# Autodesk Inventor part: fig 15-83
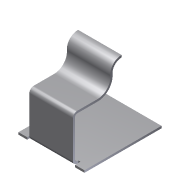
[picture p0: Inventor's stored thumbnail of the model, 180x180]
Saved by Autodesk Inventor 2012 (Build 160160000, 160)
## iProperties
Shininess: 77.0
Angle Display Precision: 2
Document Length Units: 11269
Document Angle Units: 11279
Document Time Units: 11290
Document Mass Units: 11283
Document Length Units Precision: 3
Document Angle Units Precision: 2
Compacted: True
Created: 2002-04
Part Number: fig 15-83
Document SubType Name: Sheet Metal
Density: 1 g/cm^3
Sheet Metal Rule: Default
Material: Default
Density: 0.0
Volumn: 0.0
Area: 0.0
PropertySet Name: Model Information
Control State: 0
Master: False
Checked Out: False
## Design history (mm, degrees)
node "Face1"
  sketch "Sketch1"
    geometry: L1 (-24.824, 17.882)-(5.529, 17.882); L2 (5.529, 17.882)-(5.529, -17.529); L3 (5.529, -17.529)-(-24.824, -17.529); L4 (-24.824, -17.529)-(-24.824, 17.882)
    constraints: 8 end point, 2 parallel, 1 horizontal, 1 perpendicular
node "Flange1"
node "Contour Flange6"
  sketch "Sketch5"
    geometry: L1 (0, 1)-(0, 11.431); A1 r 5.855 centre (-5.855, 11.431) between (0, 11.431) and (-6.422, 17.259); A2 r 5.142 centre (-6.92, 22.376) between (-12.062, 22.382) and (-6.422, 17.259)
    constraints: 4 point on circle, 2 centre point, 2 end point, 2 tangent
body "Solid1"
face "Plate1" dims "Thickness" = 1
sketch "Sketch3"
  geometry: L1 (25.353, 0)-(5.353, 0); L2 (5.353, 0)-(5.353, 20); L3 (5.353, 20)-(25.353, 20); L4 (25.353, 20)-(25.353, 0)
  constraints: 8 end point
face "Plate3" dims "d5" = 20, "d6" = 90 deg, "d7" = 1 (= BendRadius), "d11" = 5, "d12" = 20, "Thickness" = 1, "MinimumRemnant" = 2 (= 2 x Thickness), "BendReliefWidth" = 1 (= Thickness)
bend "Bend2" dims "d5" = 20, "d6" = 90 deg, "d7" = 1 (= BendRadius), "d21" = 1 (= BendReliefWidth), "d22" = 0.5 (= BendReliefDepth), "d23" = 2 (= MinimumRemnant), "SeamGap" = 0.01, "Thickness" = 1, "MinimumRemnant" = 2 (= 2 x Thickness), "BendReliefWidth" = 1 (= Thickness), "TransitionRadius" = 1 (= BendRadius)
face "Plate8" dims "d33" = 1 (= BendReliefWidth), "d34" = 0.5 (= BendReliefDepth), "d35" = 2 (= MinimumRemnant), "d36" = 1 (= BendRadius), "d37" = 1 (= BendRadius), "d38" = 1, "d39" = 4 (= CornerReliefSize), "d40" = 1 (= GapSize), "d41" = 1 (= JacobiRadiusSize), "SeamGap" = 0.01, "Thickness" = 1
bend "Bend7" dims "d33" = 1 (= BendReliefWidth), "d34" = 0.5 (= BendReliefDepth), "d35" = 2 (= MinimumRemnant), "d36" = 1 (= BendRadius), "d37" = 1 (= BendRadius), "d38" = 1, "SeamGap" = 0.01, "Thickness" = 1
feature "Corner1" dims "d38" = 1, "d39" = 4 (= CornerReliefSize), "d40" = 1 (= GapSize), "d41" = 1 (= JacobiRadiusSize)
other parameters: "BendRadius" = 1 (= Thickness), "BendReliefDepth" = 0.5 (= 0.5 x Thickness), "CornerReliefSize" = 4 (= 4 x Thickness), "d0" = 1 (= BendRadius), "d4" = 1 (= BendRadius), "JacobiRadiusSize" = 1 (= Thickness), "GapSize" = 1 (= Thickness)
